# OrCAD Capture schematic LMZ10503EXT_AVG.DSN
size Custom; title: LMZ10503EXT 3A SIMPLE SWITCHER® Power Module with; rev: 1.0; note: Datasheet:SNVS668E     EVM: SNVA450A
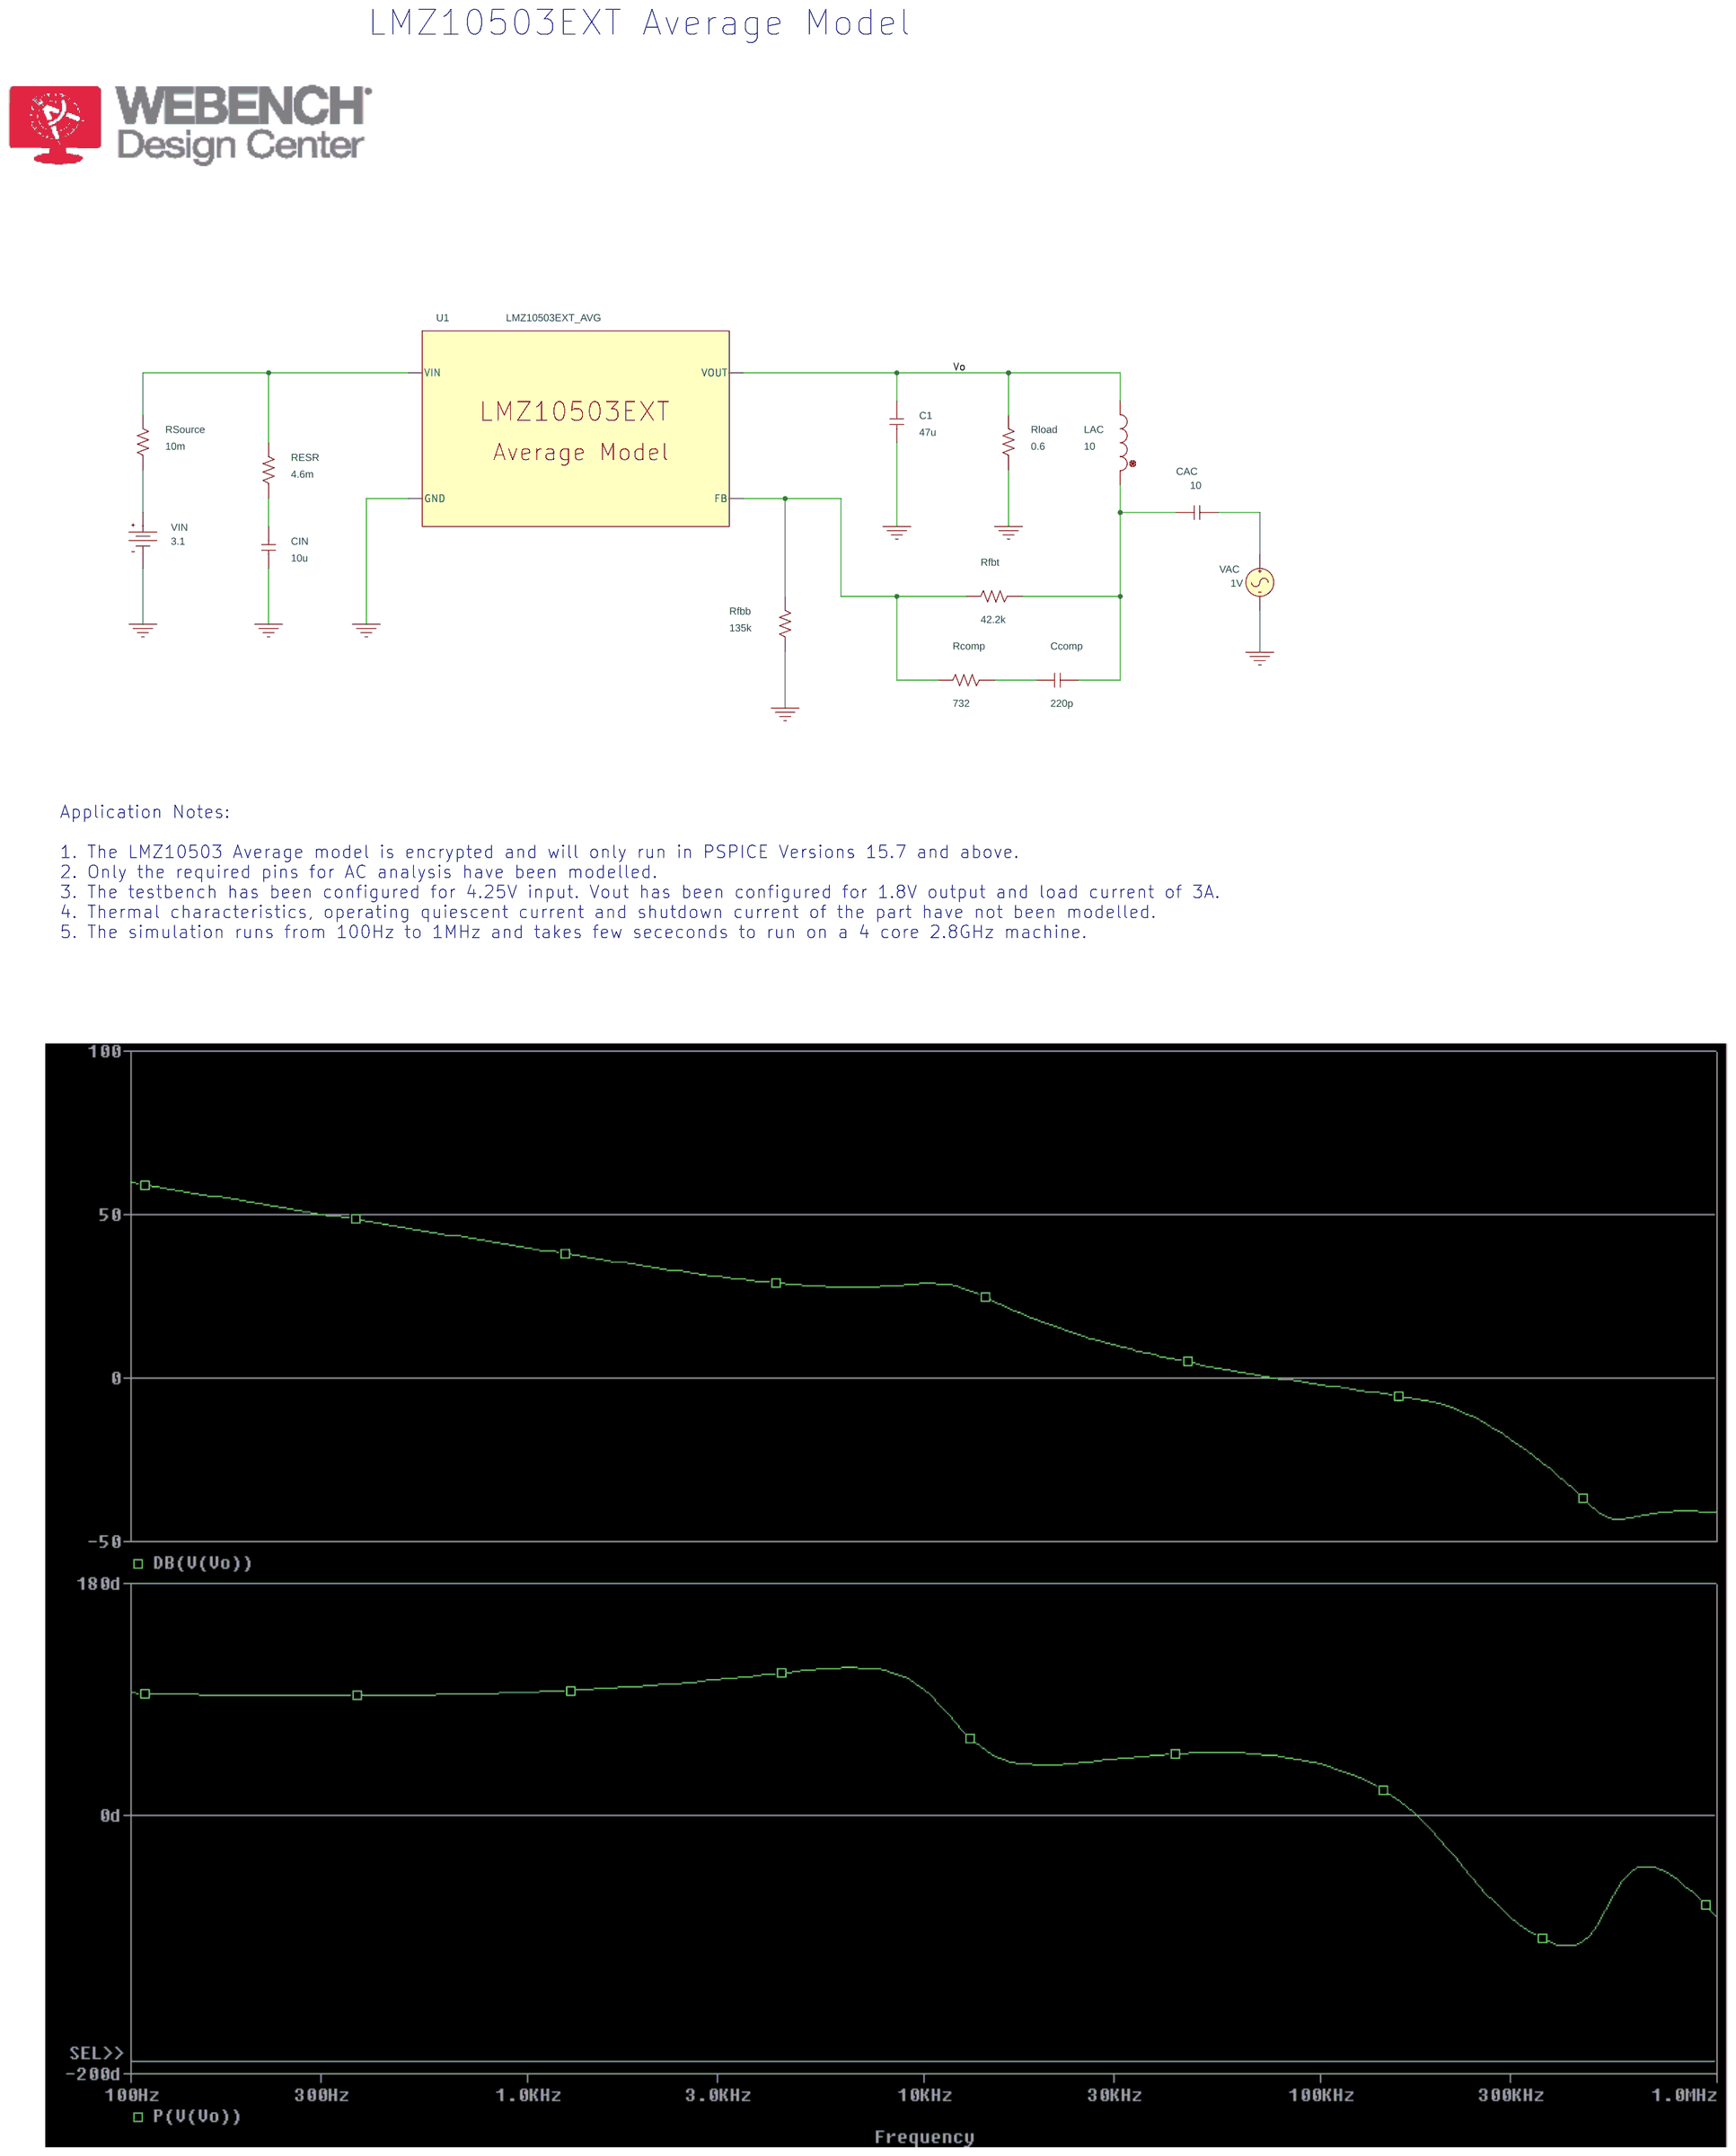
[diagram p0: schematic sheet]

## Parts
C1  47u  [cap196]
CAC  10  [RAD/CK05]
Ccomp  220p  [RAD/CK05]
CIN  10u  [RAD/CK05]
LAC  10  [DISC/.350x.175/LS.200x.100/.034]
Rcomp  732  [AX/RC05]
RESR  4.6m  [AX/RC05]
Rfbb  135k  [AX/RC05]
Rfbt  42.2k  [AX/RC05]
Rload  0.6  [AX/RC05]
RSource  10m  [AX/RC05]
U1  LMZ10503EXT_AVG
VAC  VAC
VIN  VDC

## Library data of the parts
C1 CAC Ccomp CIN = C
LAC = L
Rcomp RESR Rfbb Rfbt Rload RSource = R
U1 = LMZ10503EXT_AVG
VAC = VAC: ACMAG: 1V
VIN = VDC: DC: 3.1

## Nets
0: C1.2 CIN.1 Rfbb.1 Rload.1 U1.GND VAC.2(-) VIN.1(-)
Vo: C1.1 LAC.2 Rload.2 U1.VOUT
N14384292: CAC.1 VAC.1(+)
N14385308: CAC.2 Ccomp.1 LAC.1 Rfbt.1
N14386411: RSource.1 VIN.0(+)
N14394410: RESR.2 RSource.2 U1.VIN
N14395188: CIN.2 RESR.1
N14416131: Rcomp.2 Rfbb.2 Rfbt.2 U1.FB
N14422069: Ccomp.2 Rcomp.1

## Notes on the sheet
- LMZ10503EXT Average Model
- Application Notes:
  1. The LMZ10503 Average model is encrypted and will only run in PSPICE Versions 15.7 and above.
  2. Only the required pins for AC analysis have been modelled.
  3. The testbench has been configured for 4.25V input. Vout has been configured for 1.8V output and load current of 3A.
  4. Thermal characteristics, operating quiescent current and shutdown current of the part have not been modelled.
  5. The simulation runs from 100Hz to 1MHz and takes few sececonds to run on a 4 core 2.8GHz machine.
